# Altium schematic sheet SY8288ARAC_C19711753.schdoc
size 127 x 101 mm
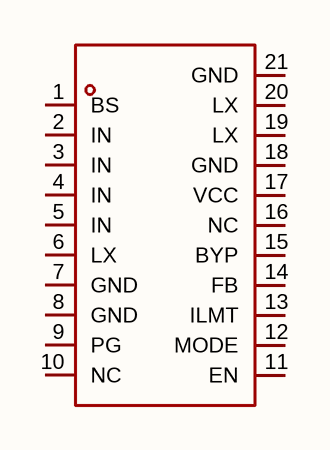
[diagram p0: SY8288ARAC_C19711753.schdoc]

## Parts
U?  sy8288arac_c19711753  [QFN-20_L3.0-W3.0-P0.45-TL-EP1.0]  (value not drawn)

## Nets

Not connected (* = marked no-connect by the designer): U? 1(BS) 2(IN) 3(IN) 4(IN) 5(IN) 6(LX) 7(GND) 8(GND) 9(PG) 10(NC) 11(EN) 12(MODE) 13(ILMT) 14(FB) 15(BYP) 16(NC) 17(VCC) 18(GND) 19(LX) 20(LX) 21(GND)

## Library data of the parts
U? = sy8288arac_c19711753: 功能类型:降压型;工作电压:4V~23V;输出电压:-;输出电流:8A;输出类型:可调;; Manufacturer: Silergy(矽力杰); AddInBom: yes; ModelId: c2b55a904ebf4102bea58dd4bc6c145f; ModelTransform: 118.11,118.11,0,0,0,0,0,0,0; Function: 降压型; Voltage - Supply: 4V~23V; Output Current: 8A; Frequency - Switching: 510kHz~690kHz; Synchronous Rectifier: 是; Number of Outputs: 1; Topology: 降压式; Quiescent Current: 145uA; Switch tube (built-in/external): 内置; Output Type: 可调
